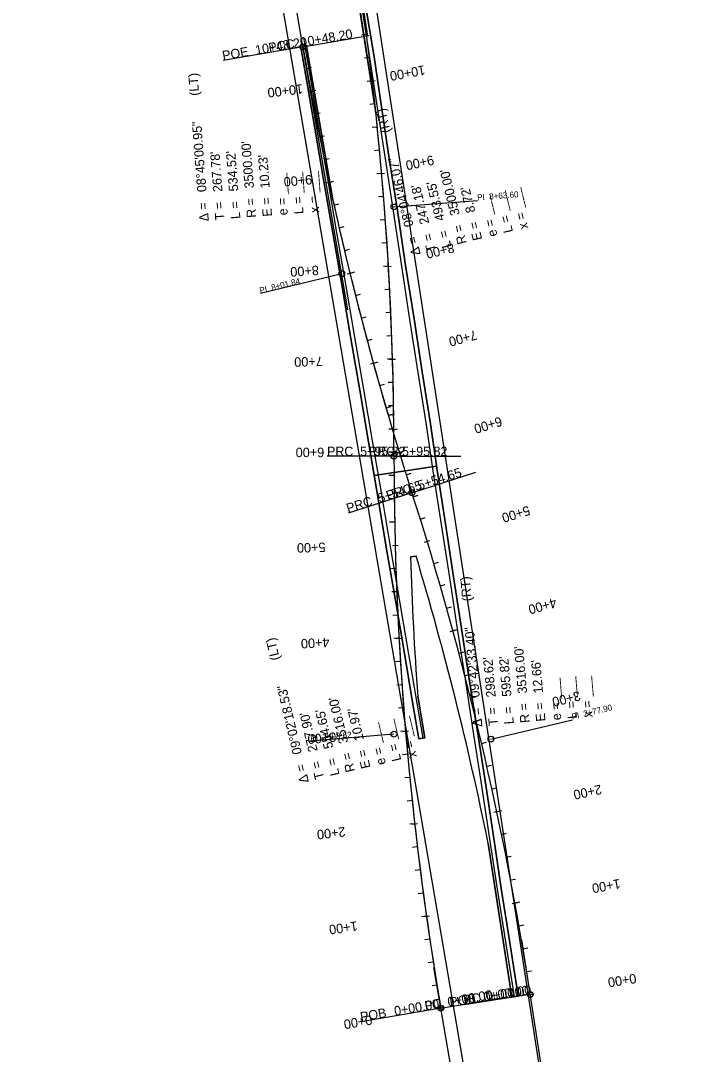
# Model space of a CAD drawing. Extents: x 11526483 to 11527252, y 9590608 to 9599499.
# Drawn here: x 11526540 to 11527252, y 9591625 to 9592736 of the extents above; entities that cross this region are included whole.
import ezdxf

# ---------------------------------------------------------------- set-up
doc = ezdxf.new("R2010")
doc.units = 0
for name, color, linetype in [('_CIVIL_CONSTRUCTION', 7, 'Continuous'), ('Alignment', 7, 'Continuous'), ('Draft_3', 7, 'Continuous'), ('EdgePaved', 7, 'Continuous'), ('Removals', 7, 'Continuous'), ('Shape', 7, 'Continuous'), ('TextAlignment', 7, 'Continuous'), ('TextAlignmentLrg', 7, 'Continuous'), ('TextAlignmentSml', 7, 'Continuous')]:
    doc.layers.add(name, color=color, linetype=linetype)

msp = doc.modelspace()

# ---------------------------------------------------------------- linework, layer by layer
at = {"layer": '_CIVIL_CONSTRUCTION'}
for p, q in [((11527252.3, 9590607.6), (11526645, 9594551)), ((11527252.3, 9590607.6), (11526645, 9594551)), ((11527165.7, 9590741), (11526539.8, 9594397.6)), ((11527165.7, 9590741), (11526539.8, 9594397.6))]:
    msp.add_line(p, q, dxfattribs=at)
at = {"layer": 'Alignment'}
for centre, radius, start, end in [((11523441.2, 9592267.8), 3500, 0.004, 8.7543), ((11530293.1, 9593298.3), 3500, 189.7133, 197.7927), ((11530457.2, 9592268.3), 3516, 180.004, 189.7133), ((11523612.7, 9591154.4), 3516, 8.7543, 17.7927)]:
    msp.add_arc(centre, radius, start, end, dxfattribs=at)
at = {"layer": 'Draft_3'}
for p, q in [((11526913, 9592719.1), (11526828.3, 9593269.1)), ((11526891.6, 9592425.4), (11526800.9, 9592955.2)), ((11527117.1, 9591498.6), (11527078.7, 9591748.2)), ((11527025.1, 9591479.8), (11526984.2, 9591718.6))]:
    msp.add_line(p, q, dxfattribs=at)
for centre, radius, start, end in [((11523441.2, 9592267.8), 3500, 0.004, 8.7543), ((11530293.1, 9593298.3), 3500, 189.7133, 197.7927), ((11530457.2, 9592268.3), 3516, 180.004, 189.7133), ((11530457.2, 9592268.3), 3516, 180.6749, 189.7133), ((11523612.7, 9591154.4), 3516, 8.7543, 17.7927)]:
    msp.add_arc(centre, radius, start, end, dxfattribs=at)
at = {"layer": 'EdgePaved'}
for p, q in [((11526922, 9592634.6), (11526896.5, 9592799.9)), ((11526922, 9592634.6), (11526896.5, 9592799.9)), ((11526841.1, 9592707.4), (11526847.2, 9592708.4)), ((11526841.1, 9592707.4), (11526847.2, 9592708.4)), ((11526875.4, 9592543.5), (11526847.2, 9592708.4)), ((11526875.4, 9592543.5), (11526847.2, 9592708.4)), ((11526934.9, 9592312), (11526940.9, 9592312.9)), ((11526935, 9592312), (11526941, 9592312.9)), ((11526958.9, 9592159.8), (11526964.9, 9592160.7)), ((11526958.9, 9592159.8), (11526964.9, 9592160.7)), ((11526974.4, 9591965.3), (11526966.8, 9592010)), ((11526974.4, 9591965.3), (11526966.8, 9592010)), ((11526968, 9591964.2), (11526974.4, 9591965.3)), ((11526968, 9591964.2), (11526974.4, 9591965.3)), ((11526968, 9591964.2), (11526974.4, 9591965.3)), ((11527067.9, 9591686.8), (11527042.5, 9591851.8)), ((11527067.9, 9591686.8), (11527042.5, 9591851.8)), ((11527074.7, 9591687.8), (11527067.9, 9591686.8)), ((11527074.7, 9591687.8), (11527067.9, 9591686.8))]:
    msp.add_line(p, q, dxfattribs=at)
for points in [[(11526903.5, 9592801), (11526911.2, 9592748.2), (11526919.8, 9592697), (11526927.8, 9592643.5), (11526936, 9592587.8), (11526944.8, 9592532), (11526953.7, 9592472.7), (11526962.9, 9592415.4), (11526971.5, 9592358.8), (11526980.4, 9592302.8), (11526987.6, 9592253.1), (11526996.5, 9592195.2), (11527005.3, 9592138.2), (11527013.2, 9592087.6), (11527021.7, 9592031), (11527030.8, 9591974.5), (11527039.3, 9591919.1), (11527047.8, 9591862.2), (11527056.6, 9591803.5), (11527065.4, 9591747.7), (11527074.7, 9591687.8)], [(11526841.1, 9592707.4), (11526846.4, 9592676.7), (11526856.1, 9592620.4), (11526865.8, 9592563.1), (11526875.3, 9592507.8), (11526885.4, 9592450.1), (11526894.8, 9592394.6), (11526904.3, 9592338.9), (11526913.9, 9592283.4), (11526923.3, 9592226.5), (11526933.2, 9592168), (11526943.5, 9592109), (11526952.8, 9592054), (11526961.6, 9592001.7), (11526968, 9591964.2)]]:
    msp.add_lwpolyline(points, dxfattribs=at)
for centre, start, end in [((11523441.2, 9592267.8), 0.715, 6.0147), ((11523441.2, 9592267.8), 0.715, 6.0147), ((11530293.1, 9593298.3), 192.4849, 196.3814), ((11530293.1, 9593298.3), 192.4849, 196.3814), ((11530457.2, 9592268.3), 181.7771, 184.2327), ((11530457.2, 9592268.3), 181.7771, 184.2327), ((11523612.7, 9591154.4), 11.4938, 16.7105), ((11523612.7, 9591154.4), 11.4938, 16.7105)]:
    msp.add_arc(centre, 3500, start, end, dxfattribs=at)
at = {"layer": 'Removals'}
msp.add_lwpolyline([(11526911.2, 9592748.2), (11526919.8, 9592697), (11526927.8, 9592643.5), (11526936, 9592587.8), (11526944.8, 9592532), (11526953.7, 9592472.7), (11526962.9, 9592415.4), (11526971.5, 9592358.8), (11526980.4, 9592302.8), (11526987.6, 9592253.1), (11526996.5, 9592195.2), (11527005.3, 9592138.2), (11527013.2, 9592087.6), (11527021.7, 9592031), (11527030.8, 9591974.5), (11527039.3, 9591919.1), (11527047.8, 9591862.2), (11527056.6, 9591803.5), (11527065.4, 9591747.7), (11527074, 9591692.2), (11527074.7, 9591687.8), (11527070.7, 9591687.2), (11527070, 9591691.8), (11527061.3, 9591746.2), (11527052.5, 9591802.8), (11527043.6, 9591861.5), (11527035.1, 9591918.3), (11527026.5, 9591973.6), (11527017.8, 9592030.4), (11527008.9, 9592087.1), (11527001.2, 9592137.6), (11526992.3, 9592194.6), (11526983.5, 9592252.4), (11526976, 9592301.8), (11526967.2, 9592357.9), (11526958.3, 9592414.8), (11526949.7, 9592472), (11526940.6, 9592531.1), (11526931.9, 9592587.4), (11526923.5, 9592642.7), (11526915.3, 9592696.3), (11526907.4, 9592747.4)], dxfattribs=at)
msp.add_lwpolyline([(11526968, 9591964.2), (11526961.6, 9592001.7), (11526952.8, 9592054), (11526943.5, 9592109), (11526933.2, 9592168), (11526923.3, 9592226.5), (11526913.9, 9592283.4), (11526904.3, 9592338.9), (11526894.8, 9592394.6), (11526885.4, 9592450.1), (11526875.3, 9592507.8), (11526865.8, 9592563.1), (11526856.1, 9592620.4), (11526846.4, 9592676.7), (11526841.1, 9592707.4), (11526845.5, 9592708.1), (11526850.7, 9592677.4), (11526860.2, 9592621.6), (11526870.1, 9592563.8), (11526879.4, 9592508.5), (11526889.4, 9592450.8), (11526898.7, 9592396), (11526908.3, 9592339.7), (11526917.7, 9592284.6), (11526927.6, 9592227), (11526937.5, 9592168.7), (11526947.6, 9592109.9), (11526956.9, 9592055.2), (11526965.9, 9592002.5), (11526972.3, 9591964.9)], close=True, dxfattribs=at)
at = {"layer": 'Shape'}
for p, q in [((11526934.9, 9592312), (11526940.9, 9592312.9)), ((11526940.9, 9592312.9), (11526934.9, 9592312)), ((11526964.9, 9592160.7), (11526958.9, 9592159.8)), ((11526958.9, 9592159.8), (11526964.9, 9592160.7))]:
    msp.add_line(p, q, dxfattribs=at)
for points in [[(11526922, 9592634.6), (11526896.5, 9592799.9)], [(11526896.5, 9592799.9), (11526922, 9592634.6)], [(11526911.2, 9592748.2), (11526919.8, 9592697), (11526927.8, 9592643.5), (11526936, 9592587.8), (11526944.8, 9592532), (11526953.7, 9592472.7), (11526962.9, 9592415.4), (11526971.5, 9592358.8), (11526980.4, 9592302.8), (11526987, 9592257.4), (11526919.9, 9592247.1), (11526913.9, 9592283.4), (11526904.3, 9592338.9), (11526894.8, 9592394.6), (11526885.4, 9592450.1), (11526875.3, 9592507.8), (11526865.8, 9592563.1), (11526856.1, 9592620.4), (11526846.4, 9592676.7), (11526841.1, 9592707.4), (11526847.2, 9592708.4), (11526875.4, 9592543.5)], [(11527042.5, 9591851.8), (11527067.9, 9591686.8), (11527074.7, 9591687.8), (11527065.4, 9591747.7), (11527056.6, 9591803.5), (11527047.8, 9591862.2), (11527039.3, 9591919.1), (11527030.8, 9591974.5), (11527021.7, 9592031), (11527013.2, 9592087.6), (11527005.3, 9592138.2), (11526996.5, 9592195.2), (11526987.6, 9592253.1), (11526980.4, 9592302.8), (11526971.5, 9592358.8), (11526962.9, 9592415.4), (11526953.7, 9592472.7), (11526944.8, 9592532), (11526936, 9592587.8), (11526927.8, 9592643.5), (11526919.8, 9592697), (11526911.2, 9592748.2)], [(11526875.4, 9592543.5), (11526847.2, 9592708.4), (11526841.1, 9592707.4), (11526846.4, 9592676.7), (11526856.1, 9592620.4), (11526865.8, 9592563.1), (11526875.3, 9592507.8), (11526885.4, 9592450.1), (11526894.8, 9592394.6), (11526904.3, 9592338.9), (11526913.9, 9592283.4), (11526923.3, 9592226.5), (11526933.2, 9592168), (11526943.5, 9592109), (11526952.8, 9592054), (11526961.6, 9592001.7), (11526968, 9591964.2), (11526974.4, 9591965.3), (11526966.8, 9592010)], [(11526966.8, 9592010), (11526974.4, 9591965.3), (11526968, 9591964.2), (11526961.6, 9592001.7), (11526952.8, 9592054), (11526943.5, 9592109), (11526933.2, 9592168), (11526923.3, 9592226.5), (11526919.9, 9592247.1), (11526987, 9592257.4), (11526987.6, 9592253.1), (11526996.5, 9592195.2), (11527005.3, 9592138.2), (11527013.2, 9592087.6), (11527021.7, 9592031), (11527030.8, 9591974.5), (11527039.3, 9591919.1), (11527047.8, 9591862.2), (11527056.6, 9591803.5), (11527065.4, 9591747.7), (11527074.7, 9591687.8), (11527067.9, 9591686.8), (11527042.5, 9591851.8)]]:
    msp.add_lwpolyline(points, dxfattribs=at)
for centre, start, end in [((11523441.2, 9592267.8), 0.7374, 6.0147), ((11523441.2, 9592267.8), 0.7374, 6.0147), ((11530293.1, 9593298.3), 192.4528, 196.3679), ((11530293.1, 9593298.3), 192.4528, 196.3679), ((11530457.2, 9592268.3), 181.7771, 184.2327), ((11530457.2, 9592268.3), 181.7771, 184.2327), ((11523612.7, 9591154.4), 11.4938, 16.7105), ((11523612.7, 9591154.4), 11.4938, 16.7105)]:
    msp.add_arc(centre, 3500, start, end, dxfattribs=at)
at = {"layer": 'TextAlignment'}
for p, q in [((11526843.3, 9592707.8), (11526914.2, 9592719.9)), ((11526843.3, 9592707.8), (11526757.5, 9592693.1)), ((11526941.2, 9592535.8), (11527030.9, 9592542.7)), ((11526885, 9592464.1), (11526797.6, 9592442.7)), ((11526941.2, 9592268.1), (11526869.2, 9592268)), ((11526941.2, 9592268.1), (11527013.2, 9592268.1)), ((11526960.5, 9592228.8), (11527029.1, 9592250.8)), ((11526960.5, 9592228.8), (11526892, 9592206.8)), ((11527045.4, 9591964.1), (11527133, 9591984.8)), ((11526941.2, 9591969.4), (11526851.6, 9591961.8)), ((11526991.6, 9591675.1), (11527062.6, 9591687.2)), ((11527087.7, 9591689.5), (11527001.7, 9591676.2)), ((11527087.7, 9591689.5), (11527016.6, 9591678.5)), ((11526991.6, 9591675.1), (11526905.9, 9591660.4))]:
    msp.add_line(p, q, dxfattribs=at)
for centre, radius in [((11526843.3, 9592707.8), 3.12), ((11526843.3, 9592707.8), 2.67), ((11526941.2, 9592535.8), 3.12), ((11526885, 9592464.1), 3.12), ((11526941.2, 9592268.1), 3.12), ((11526941.2, 9592268.1), 3.12), ((11526960.5, 9592228.8), 3.12), ((11526960.5, 9592228.8), 3.12), ((11526941.2, 9591969.4), 3.12), ((11527045.4, 9591964.1), 3.12), ((11527087.7, 9591689.5), 3.12), ((11527087.7, 9591689.5), 2.67), ((11526991.6, 9591675.1), 3.12), ((11526991.6, 9591675.1), 2.67)]:
    msp.add_circle(centre, radius, dxfattribs=at)
at = {"layer": 'TextAlignmentLrg'}
for p, q in [((11526914.8, 9592671), (11526920.9, 9592671.7)), ((11526848.7, 9592659.7), (11526854.7, 9592660.9)), ((11526928, 9592571.9), (11526922.6, 9592571.4)), ((11526871.4, 9592562.2), (11526876.7, 9592563.4)), ((11526935.3, 9592472.1), (11526929.8, 9592471.8)), ((11526893.8, 9592464.8), (11526899.1, 9592466.1)), ((11526919, 9592368), (11526924.2, 9592369.5)), ((11526939.7, 9592372.2), (11526934.2, 9592372.1)), ((11526941.2, 9592272.2), (11526935.8, 9592272.2)), ((11526946.9, 9592272), (11526952.2, 9592273.6)), ((11526939.5, 9592172.2), (11526945.6, 9592172.3)), ((11526973.9, 9592175.7), (11526979.7, 9592177.5)), ((11527004.5, 9592080.5), (11527009.8, 9592081.9)), ((11526946.7, 9592072.3), (11526941.2, 9592072)), ((11527029.5, 9591983.7), (11527034.8, 9591985)), ((11526953.7, 9591972.6), (11526948.2, 9591972.1)), ((11527051.7, 9591886.2), (11527057, 9591887.3)), ((11526963.5, 9591873.1), (11526958.1, 9591872.5)), ((11527071.1, 9591788.1), (11527076.5, 9591789.1)), ((11526976.2, 9591773.9), (11526970.8, 9591773.1)), ((11527084.7, 9591689), (11527090.7, 9591689.9)), ((11526988.6, 9591674.6), (11526994.6, 9591675.6))]:
    msp.add_line(p, q, dxfattribs=at)
at = {"layer": 'TextAlignmentSml'}
for p, q in [((11526911.8, 9592721), (11526906.3, 9592720.3)), ((11526914.9, 9592696.2), (11526909.5, 9592695.5)), ((11526847.3, 9592684.9), (11526852.6, 9592685.9)), ((11526917.9, 9592671.3), (11526912.5, 9592670.7)), ((11526914.8, 9592671), (11526920.9, 9592671.7)), ((11526848.7, 9592659.7), (11526854.7, 9592660.9)), ((11526851.7, 9592660.3), (11526857.1, 9592661.3)), ((11526856.4, 9592635.7), (11526861.7, 9592636.8)), ((11526920.7, 9592646.5), (11526915.2, 9592645.9)), ((11526923.3, 9592621.6), (11526917.9, 9592621.1)), ((11526861.2, 9592611.2), (11526866.5, 9592612.3)), ((11526925.7, 9592596.7), (11526920.3, 9592596.2)), ((11526866.2, 9592586.7), (11526871.5, 9592587.8)), ((11526924.9, 9592571.6), (11526931, 9592572.1)), ((11526868.4, 9592561.6), (11526874.4, 9592562.9)), ((11526930.1, 9592546.9), (11526924.6, 9592546.5)), ((11526876.7, 9592537.8), (11526882, 9592539)), ((11526882.2, 9592513.4), (11526887.5, 9592514.7)), ((11526932, 9592522), (11526926.5, 9592521.6)), ((11526933.7, 9592497.1), (11526928.3, 9592496.7)), ((11526887.9, 9592489.1), (11526893.2, 9592490.4)), ((11526932.2, 9592471.9), (11526938.3, 9592472.3)), ((11526890.8, 9592464.1), (11526896.8, 9592465.5)), ((11526936.6, 9592447.2), (11526931.2, 9592446.9)), ((11526899.8, 9592440.5), (11526905.1, 9592441.9)), ((11526906, 9592416.3), (11526911.3, 9592417.7)), ((11526937.8, 9592422.2), (11526932.4, 9592421.9)), ((11526912.4, 9592392.2), (11526917.7, 9592393.6)), ((11526938.8, 9592397.2), (11526933.4, 9592397)), ((11526936.6, 9592372.1), (11526942.7, 9592372.3)), ((11526916, 9592367.2), (11526921.9, 9592368.8)), ((11526940.3, 9592347.2), (11526934.9, 9592347.1)), ((11526925.7, 9592344), (11526931, 9592345.4)), ((11526932.6, 9592319.9), (11526937.9, 9592321.4)), ((11526940.8, 9592322.2), (11526935.3, 9592322.1)), ((11526941.1, 9592297.2), (11526935.6, 9592297.2)), ((11526939.7, 9592295.9), (11526944.9, 9592297.5)), ((11526938.2, 9592272.2), (11526944.3, 9592272.2)), ((11526944, 9592271.1), (11526949.9, 9592272.9)), ((11526941.3, 9592247.2), (11526935.8, 9592247.2)), ((11526954.3, 9592248.1), (11526959.6, 9592249.8)), ((11526961.9, 9592224.3), (11526967.1, 9592226)), ((11526941.5, 9592222.2), (11526936.1, 9592222.2)), ((11526941.9, 9592197.2), (11526936.5, 9592197.1)), ((11526969.4, 9592200.5), (11526974.7, 9592202.1)), ((11526939.5, 9592172.2), (11526945.6, 9592172.3)), ((11526973.9, 9592175.7), (11526979.7, 9592177.5)), ((11526943.3, 9592147.3), (11526937.8, 9592147.1)), ((11526984, 9592152.6), (11526989.2, 9592154.2)), ((11526991, 9592128.6), (11526996.2, 9592130.2)), ((11526944.3, 9592122.3), (11526938.8, 9592122.1)), ((11526997.8, 9592104.6), (11527003.1, 9592106.1)), ((11526945.4, 9592097.3), (11526939.9, 9592097)), ((11527001.6, 9592079.7), (11527007.5, 9592081.3)), ((11526943.6, 9592072.2), (11526949.7, 9592072.5)), ((11526948.2, 9592047.4), (11526942.7, 9592047)), ((11527011, 9592056.4), (11527016.3, 9592057.8)), ((11527017.3, 9592032.2), (11527022.6, 9592033.5)), ((11526949.8, 9592022.4), (11526944.4, 9592022.1)), ((11527023.5, 9592007.9), (11527028.8, 9592009.3)), ((11526951.7, 9591997.5), (11526946.2, 9591997.1)), ((11527026.5, 9591983), (11527032.5, 9591984.4)), ((11526950.6, 9591972.3), (11526956.7, 9591972.8)), ((11527035.3, 9591959.4), (11527040.6, 9591960.6)), ((11526955.9, 9591947.7), (11526950.4, 9591947.2)), ((11527040.9, 9591935), (11527046.2, 9591936.2)), ((11526958.2, 9591922.8), (11526952.8, 9591922.3)), ((11527046.4, 9591910.6), (11527051.7, 9591911.8)), ((11526960.8, 9591897.9), (11526955.4, 9591897.3)), ((11527048.7, 9591885.5), (11527054.7, 9591886.8)), ((11526960.5, 9591872.7), (11526966.5, 9591873.4)), ((11527056.8, 9591861.7), (11527062.1, 9591862.8)), ((11526966.4, 9591848.2), (11526961, 9591847.6)), ((11527061.7, 9591837.2), (11527067.1, 9591838.3)), ((11526969.5, 9591823.4), (11526964.1, 9591822.7)), ((11527066.5, 9591812.7), (11527071.9, 9591813.7)), ((11526972.7, 9591798.6), (11526967.3, 9591797.9)), ((11527068.1, 9591787.5), (11527074.1, 9591788.6)), ((11526973.1, 9591773.4), (11526979.2, 9591774.3)), ((11527075.5, 9591763.5), (11527080.9, 9591764.4)), ((11526979.8, 9591749.1), (11526974.4, 9591748.3)), ((11527079.8, 9591738.8), (11527085.1, 9591739.7)), ((11526983.5, 9591724.4), (11526978.1, 9591723.6)), ((11527083.8, 9591714.2), (11527089.2, 9591715)), ((11526987.5, 9591699.7), (11526982.1, 9591698.9)), ((11527084.7, 9591689), (11527090.7, 9591689.9)), ((11526988.6, 9591674.6), (11526994.6, 9591675.6))]:
    msp.add_line(p, q, dxfattribs=at)

# ---------------------------------------------------------------- texts
at = {"layer": 'TextAlignment'}
for s, height, rotation, p in [('10+48.20', 10.02, 9.7133, (11526841.8, 9592707.7)), ('10+48.20', 10.02, 9.7133, (11526792.9, 9592699.3)), ('PCC', 10.02, 9.7133, (11526807.2, 9592701.8)), ('POE ', 10.02, 9.7133, (11526757.5, 9592693.3)), (' (LT)', 10.02, 94.3791, (11526732.1, 9592651.9)), (' (RT)', 10.02, 103.753, (11526938.6, 9592612.9)), ('08°45\'00.95"', 10.02, 94.3791, (11526739.7, 9592552.2)), ("3500.00'", 10.02, 94.3791, (11526790.7, 9592556.1)), ("267.78'", 10.02, 94.3791, (11526756.8, 9592552.3)), ("534.52'", 10.02, 94.3791, (11526773.8, 9592553)), ("10.23'", 10.02, 94.3791, (11526807.7, 9592556.2)), ('08°04\'46.07"', 10.02, 103.753, (11526962.4, 9592515.7)), ('e = ___ ', 10.02, 94.3791, (11526827, 9592527.1)), ('L = ___', 10.02, 94.3791, (11526844, 9592528.4)), ('x = ___', 10.02, 94.3791, (11526861, 9592529.7)), ("3500.00'", 10.02, 103.753, (11527012, 9592527.8)), ("247.18'", 10.02, 103.753, (11526979.2, 9592518.5)), ("493.55'", 10.02, 103.753, (11526995.9, 9592522)), ("8.72'", 10.02, 103.753, (11527028.8, 9592530.7)), ('PI ', 6.48, 4.3791, (11527030.9, 9592542.8)), ('e = ___ ', 10.02, 103.753, (11527052.6, 9592505.1)), ('8+63.60', 6.48, 4.3791, (11527043.8, 9592543.8)), ('L = ___', 10.02, 103.753, (11527069.2, 9592509.2)), ('x = ___', 10.02, 103.753, (11527085.7, 9592513.2)), ('Δ = ', 10.02, 94.3791, (11526742.1, 9592520.6)), ('T = ', 10.02, 94.3791, (11526759.1, 9592521.9)), ('L = ', 10.02, 94.3791, (11526776.1, 9592523.2)), ('R = ', 10.02, 94.3791, (11526793.1, 9592524.5)), ('E = ', 10.02, 94.3791, (11526810.1, 9592525.8)), ('R = ', 10.02, 103.753, (11527019.5, 9592497)), ('E = ', 10.02, 103.753, (11527036.1, 9592501.1)), ('Δ = ', 10.02, 103.753, (11526969.9, 9592484.9)), ('T = ', 10.02, 103.753, (11526986.4, 9592488.9)), ('L = ', 10.02, 103.753, (11527003, 9592493)), ('8+01.84', 6.48, 13.753, (11526810.1, 9592445.9)), ('PI ', 6.48, 13.753, (11526797.5, 9592442.8)), ('PRC', 10.02, 0.004, (11526869.2, 9592268.2)), ('5+95.82', 10.02, 0.004, (11526904.8, 9592268.2)), ('PRC', 10.02, 0.004, (11526914.3, 9592268.2)), ('5+95.82', 10.02, 0.004, (11526949.8, 9592268.2)), ('5+54.65', 10.02, 17.7927, (11526968.4, 9592231.5)), ('5+54.65', 10.02, 17.7927, (11526925.7, 9592217.8)), ('PRC', 10.02, 17.7927, (11526934.6, 9592220.6)), ('PRC', 10.02, 17.7927, (11526891.9, 9592206.9)), (' (RT)', 10.02, 94.8586, (11527025, 9592108.8)), ('09°42\'33.40"', 10.02, 94.8586, (11527033.5, 9592009.1)), (' (LT)', 10.02, 103.2735, (11526819.4, 9592046.2)), ("3516.00'", 10.02, 94.8586, (11527084.4, 9592013.4)), ("298.62'", 10.02, 94.8586, (11527050.6, 9592009.3)), ("595.82'", 10.02, 94.8586, (11527067.6, 9592010.1)), ("12.66'", 10.02, 94.8586, (11527101.5, 9592013.6)), ('e = ___ ', 10.02, 94.8586, (11527121.1, 9591984.7)), ('L = ___', 10.02, 94.8586, (11527138, 9591986.2)), ('x = ___', 10.02, 94.8586, (11527155, 9591987.6)), ('09°02\'18.53"', 10.02, 103.2735, (11526842.4, 9591948.8)), ("3516.00'", 10.02, 103.2735, (11526892.1, 9591960.5)), ('E = ', 10.02, 94.8586, (11527104.1, 9591983.3)), ("277.90'", 10.02, 103.2735, (11526859.2, 9591951.5)), ("554.65'", 10.02, 103.2735, (11526876, 9591954.8)), ("10.97'", 10.02, 103.2735, (11526909, 9591963.3)), ('Δ = ', 10.02, 94.8586, (11527036.2, 9591977.5)), ('T = ', 10.02, 94.8586, (11527053.2, 9591978.9)), ('L = ', 10.02, 94.8586, (11527070.1, 9591980.4)), ('R = ', 10.02, 94.8586, (11527087.1, 9591981.8)), ('PI ', 6.48, 13.2735, (11527133, 9591984.9)), ('2+77.90', 6.48, 13.2735, (11527145.6, 9591987.9)), ('e = ___ ', 10.02, 103.2735, (11526932.6, 9591937.5)), ('L = ___', 10.02, 103.2735, (11526949.1, 9591941.4)), ('x = ___', 10.02, 103.2735, (11526965.7, 9591945.3)), ('2+98.62', 6.48, 4.8586, (11526864.4, 9591963)), ('PI ', 6.48, 4.8586, (11526851.6, 9591961.9)), ('R = ', 10.02, 103.2735, (11526899.4, 9591929.7)), ('E = ', 10.02, 103.2735, (11526916, 9591933.6)), ('Δ = ', 10.02, 103.2735, (11526849.7, 9591918)), ('T = ', 10.02, 103.2735, (11526866.2, 9591921.9)), ('L = ', 10.02, 103.2735, (11526882.8, 9591925.8)), ('0+00.00', 10.02, 9.7133, (11526999.6, 9591676.6)), ('0+00.00', 10.02, 8.7543, (11527038.3, 9591682.1)), ('0+00.00', 10.02, 8.7543, (11527041.2, 9591682.5)), ('0+00.00', 10.02, 9.7133, (11526942.3, 9591666.8)), ('PC', 10.02, 9.7133, (11526975, 9591672.4)), ('POB ', 10.02, 8.7543, (11527001.7, 9591676.4)), ('PC', 10.02, 8.7543, (11527016.5, 9591678.7)), ('POB ', 10.02, 9.7133, (11526905.8, 9591660.6))]:
    msp.add_text(s, height=height, rotation=rotation, dxfattribs=at).set_placement(p)
at = {"layer": 'TextAlignmentLrg'}
for s, rotation, p in [('10+00', 190.5023, (11526973.7, 9592688.1)), ('10+00', 186.6206, (11526842.8, 9592667.8)), ('5+00', 196.9021, (11527085.6, 9592215)), ('5+00', 181.5654, (11526867.4, 9592175.3)), ('0+00', 188.7543, (11527200.9, 9591712.1)), ('0+00', 189.7133, (11526916.8, 9591667.5))]:
    msp.add_text(s, height=10.2, rotation=rotation, dxfattribs=at).set_placement(p)
at = {"layer": 'TextAlignmentSml'}
for s, rotation, p in [('10+00', 190.5023, (11526973.7, 9592688.1)), ('10+00', 186.6206, (11526842.8, 9592667.8)), ('9+00', 192.1393, (11526983, 9592591.5)), ('9+00', 184.9835, (11526852.8, 9592570.4)), ('8+00', 193.7764, (11527004.5, 9592497.2)), ('8+00', 183.3465, (11526860.1, 9592472.8)), ('7+00', 195.4134, (11527028.8, 9592403.6)), ('7+00', 181.7095, (11526864.5, 9592375.1)), ('6+00', 197.0504, (11527055.6, 9592310.7)), ('6+00', 180.0725, (11526866.2, 9592277.2)), ('5+00', 196.9021, (11527085.6, 9592215)), ('5+00', 181.5654, (11526867.4, 9592175.3)), ('4+00', 195.2726, (11527114.4, 9592115.8)), ('4+00', 183.195, (11526871.5, 9592073.2)), ('3+00', 193.643, (11527140.3, 9592015.8)), ('3+00', 184.8246, (11526878.5, 9591971.4)), ('2+00', 192.0134, (11527163.4, 9591915.2)), ('2+00', 186.4541, (11526888.4, 9591869.7)), ('1+00', 190.3838, (11527183.6, 9591813.9)), ('1+00', 188.0837, (11526901.2, 9591768.4)), ('0+00', 188.7543, (11527200.9, 9591712.1)), ('0+00', 189.7133, (11526916.8, 9591667.5))]:
    msp.add_text(s, height=10.2, rotation=rotation, dxfattribs=at).set_placement(p)

doc.saveas('drawing.dxf')
